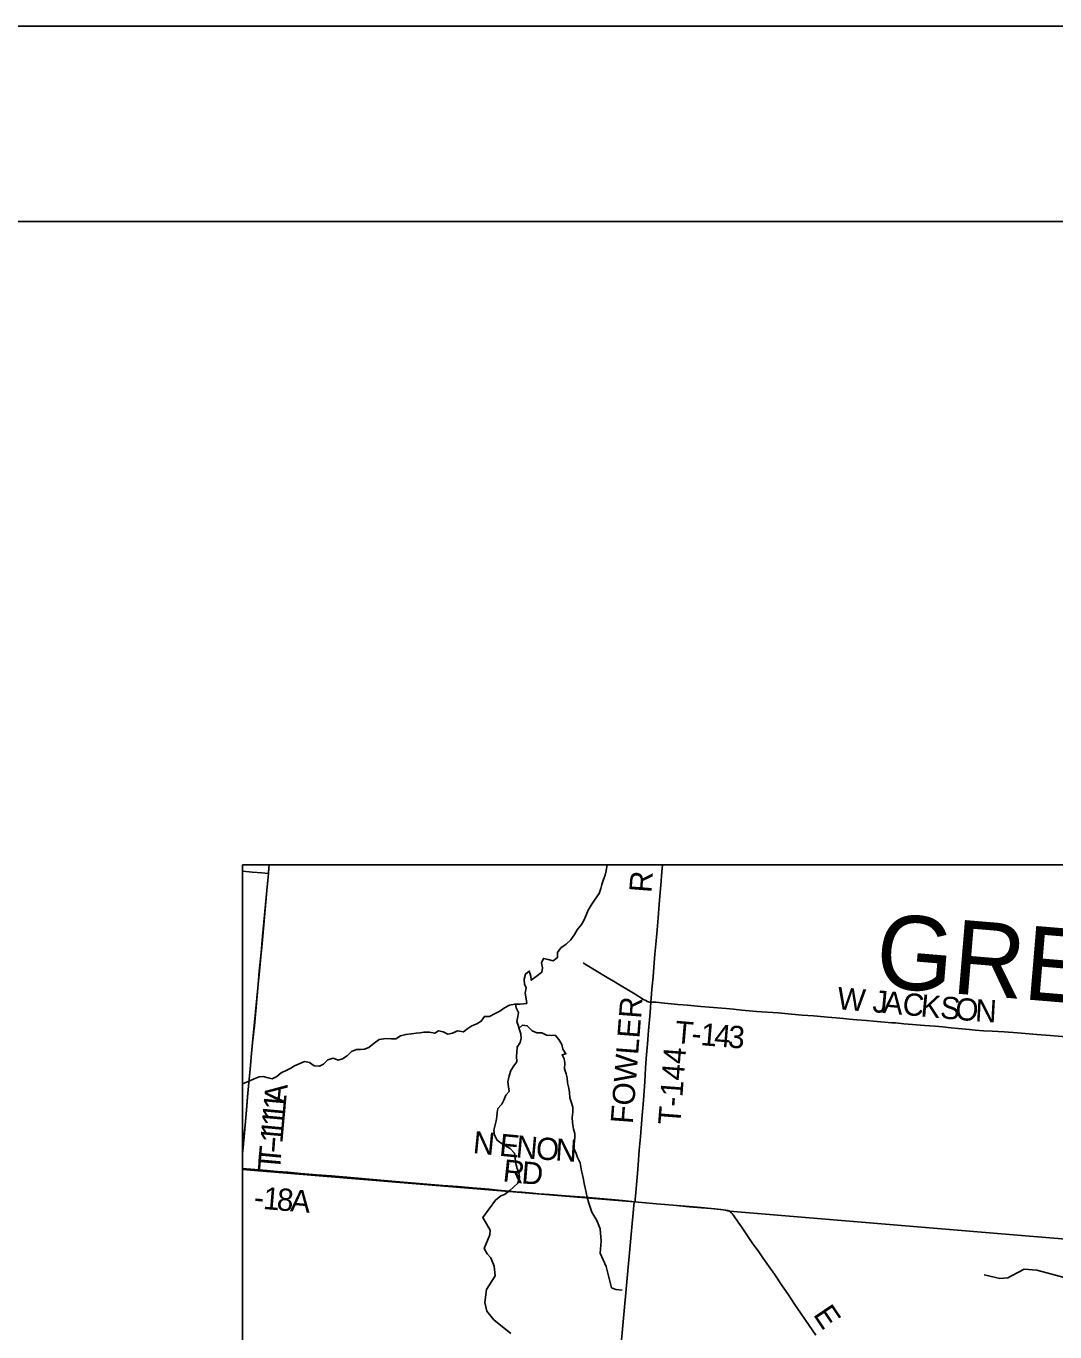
# Model space of a CAD drawing. Extents: x -1.4 to 35.4, y 0 to 22.
# Drawn here: x 16.506 to 19.136, y 18.66 to 22 of the extents above; entities that cross this region are included whole.
import ezdxf

# ---------------------------------------------------------------- set-up
doc = ezdxf.new("R2010")
doc.units = 0
for name, color, linetype in [('GM_X_County_Road', 7, 'Continuous'), ('GM_X_County_Road_Text', 7, 'Continuous'), ('GM_X_County_Text', 7, 'Continuous'), ('GM_X_Minor_River', 7, 'Continuous'), ('GM_X_Township_Road', 7, 'Continuous'), ('GM_X_Township_Road_Text', 7, 'Continuous'), ('SC_Scratch1', 7, 'Continuous'), ('SH_Border', 7, 'Continuous'), ('SH_Cut_Line', 7, 'Continuous')]:
    doc.layers.add(name, color=color, linetype=linetype)

msp = doc.modelspace()

# ---------------------------------------------------------------- linework, layer by layer
at = {"layer": 'GM_X_County_Road'}
for points in [[(17.0598, 19.078), (17.081, 19.076), (17.1226, 19.0724), (17.1484, 19.0704), (17.1755, 19.0681), (17.2087, 19.0651), (17.2489, 19.0619), (17.2874, 19.0588), (17.327, 19.0554), (17.4125, 19.0482), (17.4708, 19.0427), (17.5718, 19.0345), (17.6105, 19.0313), (17.6477, 19.0285), (17.6908, 19.0245), (17.7124, 19.0225), (17.731, 19.0208), (17.7588, 19.0183), (17.7743, 19.0171), (17.8022, 19.0147), (17.8176, 19.0133), (17.8455, 19.0108), (17.8858, 19.0077), (17.9106, 19.006), (17.9349, 19.0043), (17.954, 19.0025), (18.0035, 18.9982), (18.0314, 18.9955), (18.0632, 18.9927)], [(18.0632, 18.9927), (18.0717, 18.9919), (18.1181, 18.9877), (18.1604, 18.9843), (18.2017, 18.9806), (18.2327, 18.9777), (18.2575, 18.9756), (18.2822, 18.9731), (18.2946, 18.9715), (18.3008, 18.9703), (18.3029, 18.9696), (18.3048, 18.9686)], [(18.5257, 18.6522), (18.518, 18.6627), (18.4862, 18.7094), (18.4711, 18.7317), (18.4553, 18.7553), (18.4396, 18.7784), (18.4196, 18.8076), (18.4042, 18.8295), (18.3899, 18.8498), (18.3776, 18.8677), (18.3647, 18.886), (18.3491, 18.9084), (18.3349, 18.9295), (18.3272, 18.9408), (18.3136, 18.9601), (18.3126, 18.9615), (18.3113, 18.9631), (18.31, 18.9645), (18.3086, 18.9658), (18.3072, 18.967), (18.3058, 18.968), (18.3048, 18.9686)]]:
    msp.add_lwpolyline(points, dxfattribs=at)
msp.add_lwpolyline([(17.0598, 19.0758), (17.0598, 18.058), (17.9683, 17.9793), (18.0613, 18.9927)], close=True, dxfattribs=at)
at = {"layer": 'GM_X_Minor_River'}
msp.add_line((17.0787, 19.3026), (17.0598, 19.2948), dxfattribs=at)
for points in [[(17.992, 19.8546), (17.9912, 19.8509), (17.9896, 19.8395), (17.9868, 19.8282), (17.9829, 19.8172), (17.9782, 19.8048), (17.9754, 19.7942), (17.9711, 19.7814), (17.9611, 19.7675), (17.9511, 19.7521), (17.9434, 19.7389), (17.9383, 19.7265), (17.9325, 19.7129), (17.9263, 19.7023), (17.9155, 19.6885), (17.9086, 19.6764)], [(17.9086, 19.6764), (17.8986, 19.6633), (17.8875, 19.6524), (17.8734, 19.6424), (17.8649, 19.6311), (17.8647, 19.6178), (17.8537, 19.6096), (17.8409, 19.6132), (17.8288, 19.6156), (17.8241, 19.6043), (17.827, 19.5918), (17.8246, 19.5804), (17.8105, 19.5692), (17.7979, 19.5599), (17.7965, 19.5706), (17.7929, 19.5831), (17.783, 19.5757), (17.7801, 19.5624), (17.7804, 19.5499), (17.7848, 19.54), (17.7823, 19.5264), (17.7852, 19.512), (17.7862, 19.5006), (17.7695, 19.4985), (17.7555, 19.4987), (17.7423, 19.4958), (17.7297, 19.4895), (17.7175, 19.481), (17.7042, 19.4735), (17.6913, 19.4669), (17.678, 19.4674), (17.6699, 19.455), (17.6585, 19.448), (17.646, 19.4428), (17.6353, 19.4365), (17.6242, 19.4275), (17.6092, 19.4304), (17.5966, 19.4245), (17.5849, 19.422), (17.5728, 19.4274), (17.5608, 19.4306), (17.5513, 19.4243), (17.5373, 19.4267), (17.5233, 19.4273), (17.5135, 19.4251), (17.5032, 19.4241), (17.4915, 19.4228), (17.4771, 19.421), (17.4639, 19.4174), (17.4517, 19.41), (17.4399, 19.4098), (17.4271, 19.4107), (17.4089, 19.4079), (17.3963, 19.3989), (17.3822, 19.3881), (17.3712, 19.3837), (17.3614, 19.3823), (17.3515, 19.3824), (17.3382, 19.3777), (17.3271, 19.3664), (17.315, 19.3586), (17.3043, 19.3557), (17.2912, 19.3601), (17.2775, 19.3565), (17.2664, 19.3448), (17.2565, 19.3397), (17.2429, 19.341), (17.2305, 19.3491), (17.2181, 19.3519), (17.2048, 19.3456), (17.193, 19.3405), (17.1835, 19.3349), (17.1728, 19.3301), (17.1588, 19.3227), (17.1477, 19.3137), (17.1355, 19.3074), (17.1254, 19.3102), (17.1129, 19.3138), (17.1019, 19.3124), (17.0898, 19.308), (17.0803, 19.3036), (17.0787, 19.3026)], [(17.7578, 19.4986), (17.7592, 19.4892), (17.7655, 19.4769), (17.7638, 19.4671), (17.761, 19.4543), (17.7643, 19.4447), (17.7672, 19.4352), (17.7716, 19.4227), (17.7722, 19.4113), (17.7691, 19.4003), (17.7621, 19.3883), (17.7612, 19.375), (17.7599, 19.3652), (17.7609, 19.3515), (17.7536, 19.3406), (17.7459, 19.3286), (17.7412, 19.315), (17.738, 19.3003), (17.7397, 19.2874), (17.741, 19.2756), (17.7326, 19.2659), (17.7275, 19.253), (17.7229, 19.2432), (17.7125, 19.232), (17.7105, 19.2218), (17.71, 19.2108), (17.708, 19.1998), (17.706, 19.19), (17.702, 19.1764), (17.7037, 19.1635), (17.7104, 19.1505), (17.7205, 19.1432), (17.7302, 19.137), (17.7438, 19.1293), (17.755, 19.1174), (17.7584, 19.0908), (17.7616, 19.0786), (17.7668, 19.0641), (17.7678, 19.0543), (17.7634, 19.0407), (17.7527, 19.0302), (17.7428, 19.022), (17.7294, 19.0119), (17.7204, 19.0087)], [(17.7666, 19.4373), (17.7753, 19.4446), (17.7877, 19.4433), (17.8, 19.4303), (17.8121, 19.4256), (17.8249, 19.425), (17.8366, 19.4196), (17.849, 19.4187), (17.8589, 19.4193), (17.8686, 19.4078), (17.876, 19.3956), (17.8788, 19.3838), (17.8866, 19.3712), (17.8768, 19.3694), (17.8823, 19.3588), (17.8833, 19.3485), (17.8831, 19.3334), (17.8871, 19.3204), (17.8893, 19.3102), (17.8906, 19.2973), (17.8935, 19.2836), (17.8956, 19.2726), (17.8962, 19.2593), (17.8998, 19.2486), (17.9038, 19.2353), (17.9044, 19.2224), (17.9028, 19.2088), (17.9037, 19.1959), (17.9058, 19.1792), (17.909, 19.1681), (17.9089, 19.1545), (17.9061, 19.1405), (17.9071, 19.1306), (17.9129, 19.1165), (17.9158, 19.1067), (17.9225, 19.0925), (17.9246, 19.0827), (17.9264, 19.0724), (17.9289, 19.0618), (17.9318, 19.05), (17.9335, 19.0401), (17.9357, 19.0287), (17.9382, 19.0165), (17.941, 19.0047), (17.9452, 18.9899)], [(17.7204, 19.0087), (17.7068, 18.9974), (17.6741, 18.9526), (17.6931, 18.9203), (17.6918, 18.9082), (17.6778, 18.8736), (17.6848, 18.8598), (17.6944, 18.8501), (17.7034, 18.8287), (17.7056, 18.804), (17.6837, 18.7692), (17.6793, 18.7359), (17.6841, 18.7134), (17.7023, 18.6914), (17.7455, 18.656)], [(17.9452, 18.9899), (17.9529, 18.9665), (17.9658, 18.945), (17.974, 18.9239), (17.9765, 18.8928), (17.9743, 18.8621), (17.9896, 18.828), (18.0032, 18.7731), (18.0138, 18.7687), (18.0304, 18.7673)], [(19.7239, 18.349), (19.706, 18.3725), (19.6755, 18.3989), (19.5929, 18.4481), (19.5689, 18.4592), (19.546, 18.4714), (19.4476, 18.5106), (19.4263, 18.524), (19.3937, 18.5379), (19.3174, 18.5672), (19.2448, 18.5903), (19.2332, 18.597), (19.2236, 18.6075), (19.2148, 18.6403), (19.2118, 18.7397), (19.1962, 18.7719), (19.1866, 18.7839), (19.1604, 18.7996), (19.09, 18.8185), (19.0582, 18.8207), (19.0273, 18.8043), (19.0165, 18.7984), (18.9961, 18.7969), (18.9554, 18.8061)]]:
    msp.add_lwpolyline(points, dxfattribs=at)
at = {"layer": 'GM_X_Township_Road'}
for points in [[(17.0598, 19.8385), (17.0601, 19.8385), (17.0842, 19.8364), (17.1089, 19.8342), (17.1261, 19.8326)], [(17.1261, 19.8326), (17.1263, 19.8354), (17.128, 19.8546)], [(18.1037, 19.5037), (18.1054, 19.5248), (18.1063, 19.5372), (18.1091, 19.5681), (18.1112, 19.5928), (18.1141, 19.6268), (18.1171, 19.6608), (18.1195, 19.6887), (18.1222, 19.7196), (18.1248, 19.7537), (18.1267, 19.7751), (18.1287, 19.803), (18.1318, 19.8371), (18.1332, 19.8546)], [(17.1079, 19.636), (17.1113, 19.6723), (17.1219, 19.7889), (17.1261, 19.8326)], [(17.0598, 19.117), (17.0613, 19.1324), (17.0637, 19.1592), (17.0666, 19.1889), (17.0699, 19.2276), (17.0728, 19.2608), (17.076, 19.298), (17.0783, 19.3227), (17.0802, 19.3413), (17.0821, 19.3629), (17.0856, 19.4), (17.09, 19.4433), (17.0997, 19.5485), (17.1028, 19.5826), (17.1072, 19.629), (17.1079, 19.636)], [(17.9304, 19.6039), (17.9356, 19.601), (17.9916, 19.5669), (18.0077, 19.5572), (18.0238, 19.5477), (18.0505, 19.5317), (18.0639, 19.5238), (18.0851, 19.5108), (18.0905, 19.5077), (18.095, 19.5054), (18.0961, 19.5048), (18.0978, 19.5042), (18.1005, 19.5039), (18.1037, 19.5037)], [(18.0632, 18.9927), (18.0636, 18.9986), (18.0651, 19.0172), (18.07, 19.0758), (18.0741, 19.1252), (18.0767, 19.1592), (18.0813, 19.2147), (18.0845, 19.2518), (18.0881, 19.3012), (18.0899, 19.3352), (18.0917, 19.3599), (18.0949, 19.3969), (18.0977, 19.4309), (18.1015, 19.4771), (18.1037, 19.5037)], [(18.1037, 19.5037), (18.1069, 19.5038), (18.1107, 19.5036), (18.1167, 19.5033), (18.1384, 19.5011), (18.1724, 19.4979), (18.1971, 19.4957), (18.2311, 19.4928), (18.2528, 19.491), (18.2961, 19.4871), (18.3146, 19.4854), (18.3363, 19.4835), (18.3734, 19.4802), (18.4292, 19.476), (18.4632, 19.4731), (18.4905, 19.4708), (18.519, 19.4683), (18.5285, 19.4675), (18.5555, 19.4652), (18.5775, 19.4635), (18.5959, 19.4616), (18.6114, 19.4602), (18.6299, 19.4587), (18.6547, 19.4567), (18.6732, 19.4551), (18.7196, 19.4512), (18.7288, 19.4504), (18.7505, 19.4483), (18.7721, 19.4466), (18.803, 19.4442), (18.8308, 19.4419), (18.8493, 19.4402), (18.871, 19.4383), (18.8895, 19.4363), (18.9173, 19.4334), (18.9328, 19.4318), (18.9544, 19.4304), (18.9761, 19.4292), (19.0071, 19.4276), (19.0412, 19.4253), (19.0907, 19.4213), (19.1248, 19.4184), (19.1651, 19.4152)], [(17.0598, 19.078), (17.081, 19.076), (17.1226, 19.0724), (17.1484, 19.0704), (17.1755, 19.0681), (17.2087, 19.0651), (17.2489, 19.0619), (17.2874, 19.0588), (17.327, 19.0554), (17.4125, 19.0482), (17.4708, 19.0427), (17.5718, 19.0345), (17.6105, 19.0313), (17.6477, 19.0285), (17.6908, 19.0245), (17.7124, 19.0225), (17.731, 19.0208), (17.7588, 19.0183), (17.7743, 19.0171), (17.8022, 19.0147), (17.8176, 19.0133), (17.8455, 19.0108), (17.8858, 19.0077), (17.9106, 19.006), (17.9349, 19.0043), (17.954, 19.0025), (18.0035, 18.9982), (18.0314, 18.9955), (18.0632, 18.9927)], [(18.0632, 18.9927), (18.0717, 18.9919), (18.1181, 18.9877), (18.1604, 18.9843), (18.2017, 18.9806), (18.2327, 18.9777), (18.2575, 18.9756), (18.2822, 18.9731), (18.2946, 18.9715), (18.3008, 18.9703), (18.3029, 18.9696), (18.3048, 18.9686)]]:
    msp.add_lwpolyline(points, dxfattribs=at)
at = {"layer": 'SC_Scratch1'}
for points in [[(21.2033, 19.8546), (17.1277, 19.8546), (17.1261, 19.8359), (17.1258, 19.8331), (17.1217, 19.7894), (17.1111, 19.6728), (17.107, 19.6295), (17.1026, 19.5831), (17.0995, 19.5491), (17.0898, 19.4439), (17.0854, 19.4006), (17.0819, 19.3634), (17.08, 19.3418), (17.0781, 19.3233), (17.0757, 19.2985), (17.0726, 19.2614), (17.0697, 19.2281), (17.0664, 19.1894), (17.0634, 19.1597), (17.061, 19.1329), (17.0598, 19.12), (17.0598, 19.0785), (17.0807, 19.0765), (17.1224, 19.073), (17.1482, 19.071), (17.1752, 19.0686), (17.2085, 19.0656), (17.2486, 19.0624), (17.2871, 19.0593), (17.3267, 19.056), (17.4123, 19.0487), (17.4706, 19.0433), (17.5716, 19.0351), (17.6103, 19.0319), (17.6475, 19.029), (17.6905, 19.025), (17.7122, 19.0231), (17.7308, 19.0213), (17.7586, 19.0188), (17.7741, 19.0176), (17.8019, 19.0153), (17.8174, 19.0138), (17.8453, 19.0114), (17.8856, 19.0082), (17.9104, 19.0065), (17.9347, 19.0048), (17.9538, 19.003), (18.0033, 18.9987), (18.0312, 18.9961), (18.0629, 18.9932), (18.0714, 18.9924), (18.1179, 18.9882), (18.1601, 18.9848), (18.2015, 18.9811), (18.2325, 18.9783), (18.2572, 18.9761), (18.282, 18.9737), (18.2944, 18.972), (18.3005, 18.9708), (18.3026, 18.9701), (18.3046, 18.9691), (19.8595, 18.8397)], [(19.8595, 18.8397), (18.3046, 18.9691), (18.3026, 18.9701), (18.3005, 18.9708), (18.2944, 18.972), (18.282, 18.9737), (18.2572, 18.9761), (18.2325, 18.9783), (18.2015, 18.9811), (18.1601, 18.9848), (18.1179, 18.9882), (18.0714, 18.9924), (18.0629, 18.9932), (18.0312, 18.9961), (18.0033, 18.9987), (17.9538, 19.003), (17.9347, 19.0048), (17.9104, 19.0065), (17.8856, 19.0082), (17.8453, 19.0114), (17.8174, 19.0138), (17.8019, 19.0153), (17.7741, 19.0176), (17.7586, 19.0188), (17.7308, 19.0213), (17.7122, 19.0231), (17.6905, 19.025), (17.6475, 19.029), (17.6103, 19.0319), (17.5716, 19.0351), (17.4706, 19.0433), (17.4123, 19.0487), (17.3267, 19.056), (17.2871, 19.0593), (17.2486, 19.0624), (17.2085, 19.0656), (17.1752, 19.0686), (17.1482, 19.071), (17.1224, 19.073), (17.0807, 19.0765), (17.0598, 19.0785), (17.0598, 16.0235)]]:
    msp.add_lwpolyline(points, dxfattribs=at)
msp.add_lwpolyline([(17.1277, 19.8546), (17.0598, 19.8546), (17.0598, 19.12), (17.061, 19.1329), (17.0634, 19.1597), (17.0664, 19.1894), (17.0697, 19.2281), (17.0726, 19.2614), (17.0757, 19.2985), (17.0781, 19.3233), (17.08, 19.3418), (17.0819, 19.3634), (17.0854, 19.4006), (17.0898, 19.4439), (17.0995, 19.5491), (17.1026, 19.5831), (17.107, 19.6295), (17.1111, 19.6728), (17.1217, 19.7894), (17.1258, 19.8331), (17.1261, 19.8359)], close=True, dxfattribs=at)
at = {"layer": 'SH_Border'}
for points in [[(1.5, 21.5), (33.5, 21.5), (33.5, 0.5), (1.5, 0.5)], [(17.0598, 19.8546), (23.8598, 19.8546), (23.8598, 13.0546), (17.0598, 13.0546)]]:
    msp.add_lwpolyline(points, close=True, dxfattribs=at)
at = {"layer": 'SH_Cut_Line'}
for points in [[(0, 0), (34, 0), (34, 22), (0, 22)], [(17.1277, 19.8546), (17.0598, 19.8546), (17.0598, 19.12), (17.061, 19.1329), (17.0634, 19.1597), (17.0664, 19.1894), (17.0697, 19.2281), (17.0726, 19.2614), (17.0757, 19.2985), (17.0781, 19.3233), (17.08, 19.3418), (17.0819, 19.3634), (17.0854, 19.4006), (17.0898, 19.4439), (17.0995, 19.5491), (17.1026, 19.5831), (17.107, 19.6295), (17.1111, 19.6728), (17.1217, 19.7894), (17.1258, 19.8331), (17.1261, 19.8359)]]:
    msp.add_lwpolyline(points, close=True, dxfattribs=at)
msp.add_lwpolyline([(23.8598, 19.8546), (17.1277, 19.8546), (17.1261, 19.8359), (17.1258, 19.8331), (17.1217, 19.7894), (17.1111, 19.6728), (17.107, 19.6295), (17.1026, 19.5831), (17.0995, 19.5491), (17.0898, 19.4439), (17.0854, 19.4006), (17.0819, 19.3634), (17.08, 19.3418), (17.0781, 19.3233), (17.0757, 19.2985), (17.0726, 19.2614), (17.0697, 19.2281), (17.0664, 19.1894), (17.0634, 19.1597), (17.061, 19.1329), (17.0598, 19.12), (17.0598, 19.0785), (17.0807, 19.0765), (17.1224, 19.073), (17.1482, 19.071), (17.1752, 19.0686), (17.2085, 19.0656), (17.2486, 19.0624), (17.2871, 19.0593), (17.3267, 19.056), (17.4123, 19.0487), (17.4706, 19.0433), (17.5716, 19.0351), (17.6103, 19.0319), (17.6475, 19.029), (17.6905, 19.025), (17.7122, 19.0231), (17.7308, 19.0213), (17.7586, 19.0188), (17.7741, 19.0176), (17.8019, 19.0153), (17.8174, 19.0138), (17.8453, 19.0114), (17.8856, 19.0082), (17.9104, 19.0065), (17.9347, 19.0048), (17.9538, 19.003), (18.0033, 18.9987), (18.0312, 18.9961), (18.0629, 18.9932), (18.0714, 18.9924), (18.1179, 18.9882), (18.1601, 18.9848), (18.2015, 18.9811), (18.2325, 18.9783), (18.2572, 18.9761), (18.282, 18.9737), (18.2944, 18.972), (18.3005, 18.9708), (18.3026, 18.9701), (18.3046, 18.9691), (19.8595, 18.8397)], dxfattribs=at)

# ---------------------------------------------------------------- texts
at = {"layer": 'GM_X_County_Road_Text'}
msp.add_text('E', height=0.0568, rotation=303.8969, dxfattribs=at).set_placement((18.5172, 18.7048))
at = {"layer": 'GM_X_County_Text'}
msp.add_text('GREENE COUNTY', height=0.189394, rotation=355.2302, dxfattribs=at).set_placement((18.6738, 19.5431))
at = {"layer": 'GM_X_Township_Road_Text'}
for s, height, rotation, p in [('R', 0.0568, 85.4404, (18.1047, 19.7822)), ('W', 0.0568, 354.9933, (18.5782, 19.486)), ('FOWLER', 0.05682, 85.5252, (18.0572, 19.1912)), ('J', 0.0568, 354.8053, (18.6688, 19.4785)), ('A', 0.0568, 354.807, (18.6954, 19.4761)), ('C', 0.0568, 354.8059, (18.7452, 19.4716)), ('K', 0.0568, 354.8061, (18.7917, 19.4674)), ('S', 0.0568, 354.8099, (18.8414, 19.4628)), ('O', 0.0568, 354.9733, (18.8798, 19.4593)), ('N', 0.0568, 356.7367, (18.9315, 19.4548)), ('T', 0.0568, 355.0698, (18.1635, 19.3997)), ('1', 0.0568, 355.1041, (18.2291, 19.394)), ('4', 0.0568, 355.2033, (18.2641, 19.391)), ('3', 0.0568, 355.603, (18.2994, 19.388)), ('-', 0.0568, 355.073, (18.2058, 19.396)), ('T-144', 0.05682, 85.5683, (18.1786, 19.1883)), ('T-11A', 0.05682, 84.653, (17.1561, 19.0865)), ('T-111', 0.05682, 84.9575, (17.1552, 19.0702)), ('N', 0.0568, 354.3224, (17.6472, 19.1178)), ('E', 0.0568, 354.3231, (17.7144, 19.1111)), ('N', 0.0568, 354.6585, (17.757, 19.1069)), ('O', 0.0568, 356.1876, (17.8084, 19.1021)), ('N', 0.0568, 356.1851, (17.8583, 19.0988)), ('R', 0.0568, 353.7488, (17.7234, 19.0457)), ('D', 0.0568, 355.3085, (17.7714, 19.0404)), ('1', 0.0568, 355.1032, (17.1108, 18.9749)), ('8', 0.0568, 355.2127, (17.1458, 18.9719)), ('A', 0.0568, 355.2448, (17.1807, 18.9689)), ('-', 0.0568, 354.871, (17.0873, 18.977))]:
    msp.add_text(s, height=height, rotation=rotation, dxfattribs=at).set_placement(p)

doc.saveas('drawing.dxf')
